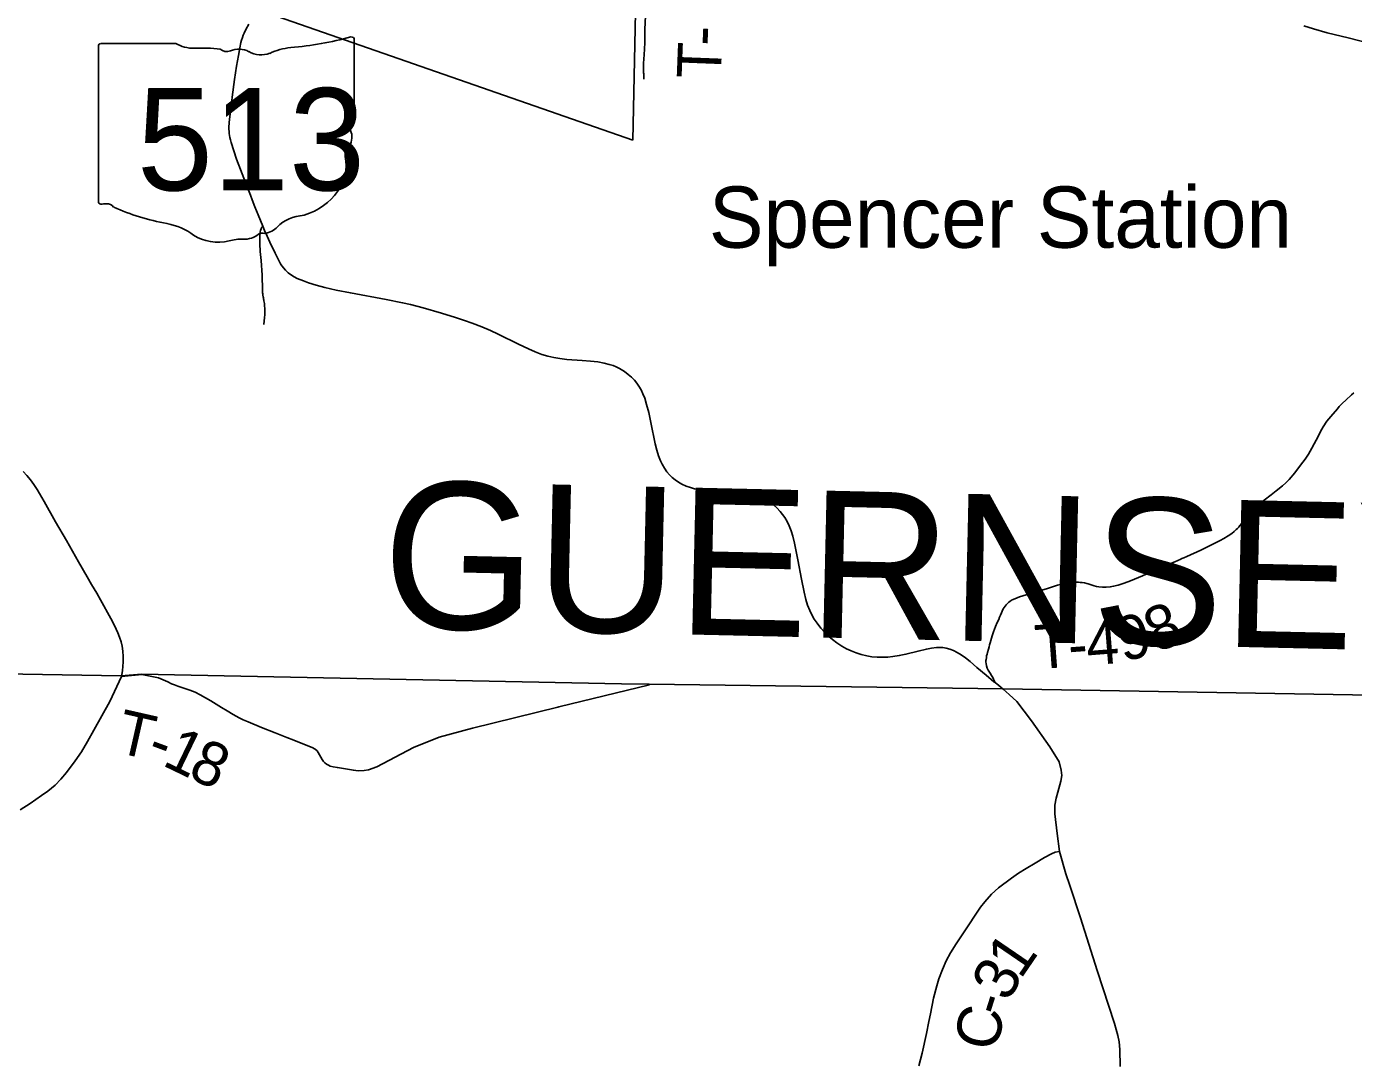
# Model space of a CAD drawing. Extents: x 0 to 34, y 0 to 22.
# Drawn here: x 3.375 to 5.085, y 18.658 to 19.997 of the extents above; entities that cross this region are included whole.
import ezdxf

# ---------------------------------------------------------------- set-up
doc = ezdxf.new("R2010")
doc.units = 0
for name, color, linetype in [('GM_X_Corporation', 7, 'Continuous'), ('GM_X_County_Road', 7, 'Continuous'), ('GM_X_County_Road_Text', 7, 'Continuous'), ('GM_X_County_Text', 7, 'Continuous'), ('GM_X_State_Location', 7, 'Continuous'), ('GM_X_State_Route', 7, 'Continuous'), ('GM_X_State_Shield', 7, 'Continuous'), ('GM_X_Township_Road', 7, 'Continuous'), ('GM_X_Township_Road_Text', 7, 'Continuous'), ('GM_X_Township_Text', 7, 'Continuous'), ('GM_X_Unincorporated_Text', 7, 'Continuous')]:
    doc.layers.add(name, color=color, linetype=linetype)

msp = doc.modelspace()

# ---------------------------------------------------------------- linework, layer by layer
at = {"layer": 'GM_X_Corporation'}
msp.add_lwpolyline([(4.156, 19.8502), (3.4056, 20.1119), (3.4116, 20.3825), (3.4113, 20.41), (3.4183, 20.6864), (3.5128, 20.6849), (3.6737, 20.6823), (4.1737, 20.6751), (4.1725, 20.6666), (4.1618, 20.1184)], close=True, dxfattribs=at)
at = {"layer": 'GM_X_County_Road'}
for points in [[(3.497, 19.1593), (3.498, 19.1637), (3.4985, 19.167), (3.499, 19.1718), (3.4994, 19.1781), (3.4993, 19.185), (3.4987, 19.1918), (3.4978, 19.1981), (3.4965, 19.2036), (3.4946, 19.2096), (3.4924, 19.2154), (3.4879, 19.225), (3.4834, 19.2339), (3.4701, 19.2579), (3.4652, 19.2665), (3.4585, 19.2777), (3.4528, 19.2874), (3.4416, 19.3067), (3.4261, 19.3343), (3.4121, 19.3585), (3.3974, 19.3845), (3.3883, 19.4), (3.3842, 19.4064), (3.3799, 19.4125), (3.3752, 19.4183), (3.3705, 19.4234)], [(3.3667, 18.9873), (3.3792, 18.9952), (3.3939, 19.0055), (3.4021, 19.0114), (3.4116, 19.0189), (3.419, 19.0266), (3.4263, 19.0354), (3.4374, 19.0504), (3.4455, 19.0621), (3.4533, 19.0752), (3.4616, 19.0899), (3.4821, 19.1267), (3.497, 19.1593)], [(4.7058, 18.9337), (4.7004, 18.9327), (4.6955, 18.9305), (4.6868, 18.9257), (4.6748, 18.9187), (4.663, 18.9118), (4.6533, 18.9056), (4.6443, 18.8991), (4.6275, 18.8868), (4.6184, 18.8784), (4.6098, 18.8687), (4.604, 18.8617), (4.5824, 18.8286), (4.5728, 18.8144), (4.5657, 18.803), (4.56, 18.7925), (4.5551, 18.7815), (4.5505, 18.7696), (4.5477, 18.7605), (4.5437, 18.7446), (4.5397, 18.7242), (4.5378, 18.7143), (4.5346, 18.6991), (4.5288, 18.6738), (4.5247, 18.6574)]]:
    msp.add_lwpolyline(points, dxfattribs=at)
at = {"layer": 'GM_X_State_Route'}
for points in [[(4.6229, 19.1512), (4.6215, 19.1523), (4.6114, 19.1606), (4.5996, 19.1708), (4.5907, 19.1785), (4.5849, 19.1831), (4.5794, 19.187), (4.5741, 19.1902), (4.5692, 19.1927), (4.5647, 19.1944), (4.56, 19.1957), (4.5558, 19.1963), (4.5521, 19.1965), (4.5473, 19.1964), (4.5412, 19.1957), (4.5345, 19.1945), (4.5237, 19.1918), (4.508, 19.1878), (4.4994, 19.186), (4.4914, 19.1848), (4.4846, 19.1841), (4.4783, 19.1839), (4.4708, 19.184), (4.464, 19.1846), (4.4578, 19.1856), (4.4504, 19.1873), (4.4439, 19.1894), (4.4375, 19.192), (4.4313, 19.1949), (4.4253, 19.1983), (4.419, 19.2024), (4.4136, 19.2066), (4.4088, 19.2106), (4.4035, 19.2159), (4.3985, 19.2215), (4.3936, 19.2279), (4.39, 19.2331), (4.3869, 19.2385), (4.3841, 19.2441), (4.3814, 19.2511), (4.3792, 19.2583), (4.3769, 19.268), (4.3736, 19.2845), (4.3688, 19.3095), (4.3645, 19.3308), (4.3623, 19.3398), (4.3601, 19.3468), (4.3576, 19.3531), (4.355, 19.3587), (4.3519, 19.364), (4.3492, 19.3681), (4.3461, 19.3719), (4.3419, 19.3763), (4.3373, 19.3803), (4.3323, 19.384), (4.3271, 19.3873), (4.3217, 19.3902), (4.3167, 19.3925), (4.3109, 19.3945), (4.305, 19.396), (4.2983, 19.3971), (4.2897, 19.3977), (4.273, 19.3983), (4.255, 19.3986), (4.2487, 19.3989), (4.2419, 19.3997), (4.2357, 19.401), (4.2303, 19.4025), (4.225, 19.4045), (4.2193, 19.4071), (4.2149, 19.4096), (4.2107, 19.4124), (4.2068, 19.4156), (4.2033, 19.4192), (4.2, 19.423), (4.1968, 19.4277), (4.1939, 19.4326), (4.1917, 19.4371), (4.1891, 19.4435), (4.1869, 19.4507), (4.1849, 19.4592), (4.1795, 19.4866), (4.1766, 19.4993), (4.1739, 19.5095), (4.1714, 19.5178), (4.1692, 19.5235), (4.1668, 19.5285), (4.164, 19.5332), (4.1612, 19.5373), (4.1581, 19.541), (4.1543, 19.545), (4.1501, 19.5485), (4.1452, 19.5521), (4.1389, 19.556), (4.1347, 19.5582), (4.1308, 19.5598), (4.1256, 19.5614), (4.119, 19.5631), (4.1112, 19.5645), (4.1014, 19.5656), (4.091, 19.5663), (4.0712, 19.5679), (4.0619, 19.5689), (4.0545, 19.5701), (4.0466, 19.5719), (4.0389, 19.5743), (4.0301, 19.5776), (4.0216, 19.5813), (4.0087, 19.5875), (3.9826, 19.6004), (3.9725, 19.6051), (3.9617, 19.6097), (3.949, 19.6146), (3.9391, 19.6181), (3.9274, 19.622), (3.9096, 19.6274), (3.8857, 19.6342), (3.8695, 19.6385), (3.8593, 19.6409), (3.838, 19.6451), (3.7922, 19.6535), (3.7739, 19.6572), (3.7593, 19.6606), (3.7479, 19.6637), (3.7383, 19.6666), (3.7318, 19.6689), (3.7237, 19.6723), (3.7198, 19.6742), (3.715, 19.6772), (3.712, 19.6796), (3.7083, 19.6829), (3.7039, 19.6883), (3.7022, 19.6909), (3.699, 19.697), (3.695, 19.7046), (3.6884, 19.7189), (3.6847, 19.7268), (3.6815, 19.734), (3.6791, 19.7394), (3.6731, 19.7541), (3.6689, 19.7645), (3.6654, 19.7737), (3.6632, 19.7795), (3.6599, 19.7882), (3.6504, 19.8125), (3.6455, 19.8259), (3.6419, 19.8365), (3.6385, 19.8472), (3.6376, 19.8508), (3.6369, 19.8537), (3.6364, 19.8565), (3.636, 19.8589), (3.6358, 19.8616), (3.6356, 19.8646), (3.6356, 19.8664), (3.6356, 19.8689), (3.6357, 19.871), (3.6359, 19.8733), (3.6377, 19.8881), (3.6384, 19.8934), (3.6388, 19.8979), (3.6393, 19.9016), (3.6398, 19.9059), (3.6428, 19.9286), (3.6454, 19.9456), (3.6477, 19.9596), (3.6495, 19.9694), (3.651, 19.9761), (3.6518, 19.9791), (3.6529, 19.9826), (3.654, 19.9856), (3.6552, 19.9885), (3.6573, 19.993), (3.661, 19.9998)], [(5.0207, 19.9976), (5.0332, 19.9938), (5.0511, 19.9889), (5.0782, 19.9821), (5.1096, 19.9743)], [(4.6336, 19.1427), (4.6279, 19.1475), (4.6229, 19.1512)], [(4.7842, 18.6565), (4.7836, 18.6785), (4.7828, 18.6884), (4.7813, 18.6964), (4.7769, 18.7119), (4.7546, 18.7801), (4.733, 18.8482), (4.7194, 18.8895), (4.7142, 18.9049), (4.7058, 18.9337), (4.7028, 18.9566), (4.7, 18.982), (4.6998, 18.9933), (4.7015, 19.0022), (4.7038, 19.0101), (4.7078, 19.0243), (4.7088, 19.0313), (4.7083, 19.0384), (4.7054, 19.0489), (4.6934, 19.0685), (4.67, 19.102), (4.6511, 19.1269), (4.641, 19.136), (4.6336, 19.1427)]]:
    msp.add_lwpolyline(points, dxfattribs=at)
at = {"layer": 'GM_X_State_Shield'}
for p, q in [((3.5672, 19.9751), (3.4707, 19.9751)), ((3.797, 19.8754), (3.797, 19.9801)), ((3.4674, 19.9717), (3.4674, 19.7716)), ((3.797, 19.8754), (3.797, 19.8754))]:
    msp.add_line(p, q, dxfattribs=at)
for centre, major_axis, start_param, end_param in [((3.4712, 19.9721), (0.00382, 0), 1.712693, 3.28349), ((3.5902, 19.9984), (0.037, 0), 4.042523, 4.731795), ((3.6796, 20.248), (0.3495, 0), 4.814394, 5.042369), ((3.7933, 19.9805), (0.00367, 0), 6.141152, 7.989035), ((3.6024, 19.8628), (0.133, 0), 1.404758, 1.657858), ((3.6326, 19.9732), (0.0107, 0), 3.836095, 5.185415), ((3.6483, 19.95), (0.0222, 0), 0.950623, 2.079405), ((3.677, 19.9818), (0.0267, 0), 4.081561, 5.145723), ((3.7242, 19.914), (0.0703, 0), 1.699011, 2.107814), ((3.7962, 19.8677), (0.00568, 0), 1.883978, 3.671073), ((3.7931, 19.875), (0.00393, 0), 5.05454, 6.418171), ((3.76, 19.8545), (0.0341, 0), 5.934695, 6.695948), ((3.8101, 19.8316), (0.0248, 0), 2.387724, 3.262537), ((3.6992, 19.8183), (0.0874, 0), 5.101752, 6.440018), ((3.4712, 19.7711), (0.00385, 0), 3.00124, 4.508301), ((3.4718, 19.7916), (0.0294, 0), 4.665946, 4.897461), ((3.4778, 19.76), (0.0106, 0), 0.519207, 1.627899), ((3.6117, 19.9398), (0.2524, 0), 4.195997, 4.488961), ((3.736, 19.7154), (0.0479, 0), 1.647645, 2.488434), ((3.5364, 19.6817), (0.079, 0), 0.823519, 1.323587), ((3.6754, 19.7522), (0.0282, 0), 4.937069, 5.64225), ((3.6218, 19.759), (0.0501, 0), 4.026481, 4.996735), ((3.6508, 19.6898), (0.0412, 0), 1.495662, 1.94098), ((3.6544, 19.744), (0.0267, 0), 4.691044, 5.507374), ((3.6786, 19.7247), (0.00752, 0), 1.147584, 2.315152)]:
    msp.add_ellipse(centre, major_axis=major_axis, ratio=0.8, start_param=start_param, end_param=end_param, dxfattribs=at)
at = {"layer": 'GM_X_Township_Road'}
msp.add_line((4.0606, 19.1199), (4.1775, 19.1485), dxfattribs=at)
for points in [[(4.1701, 19.9291), (4.1701, 19.9321), (4.1701, 19.9357), (4.17, 19.9374), (4.17, 19.9392), (4.1699, 19.941), (4.1698, 19.9428), (4.1698, 19.9447), (4.1699, 19.9473), (4.17, 19.9496), (4.1703, 19.9546), (4.1707, 19.9607), (4.1711, 19.9675), (4.1715, 19.9761), (4.1716, 19.9793), (4.1717, 19.9829), (4.1716, 19.986), (4.1716, 19.9896), (4.1717, 19.9921), (4.1717, 19.9934), (4.1725, 20.0101)], [(3.6807, 19.6127), (3.6814, 19.6217), (3.6817, 19.6252), (3.6819, 19.6278), (3.682, 19.6307), (3.6819, 19.6334), (3.6816, 19.6368), (3.6813, 19.6397), (3.681, 19.6416), (3.6807, 19.6432), (3.6805, 19.6445), (3.6803, 19.6456), (3.68, 19.647), (3.6797, 19.6483), (3.6794, 19.6504), (3.6792, 19.6522), (3.679, 19.6536), (3.6789, 19.6552), (3.6788, 19.6568), (3.6788, 19.6584), (3.6788, 19.6597), (3.6787, 19.6617), (3.6785, 19.6716), (3.6783, 19.6764), (3.6771, 19.6951), (3.676, 19.7068), (3.6754, 19.7168), (3.6754, 19.7249), (3.6755, 19.7277), (3.6758, 19.7304), (3.676, 19.7323), (3.6764, 19.7341), (3.6769, 19.7362), (3.6772, 19.737), (3.6775, 19.7376), (3.6779, 19.7383), (3.6784, 19.7389), (3.6791, 19.7394)], [(4.6229, 19.1512), (4.6209, 19.1557), (4.62, 19.1576), (4.6185, 19.1604), (4.6167, 19.1635), (4.6142, 19.1671), (4.6128, 19.1698), (4.6118, 19.1727), (4.6113, 19.1758), (4.6112, 19.1774), (4.6112, 19.1795), (4.6114, 19.1812), (4.6117, 19.1832), (4.6121, 19.1856), (4.6127, 19.188), (4.6133, 19.1902), (4.6143, 19.1942), (4.6152, 19.1973), (4.6158, 19.1998), (4.6166, 19.2026), (4.6174, 19.2053), (4.6184, 19.2087), (4.6193, 19.2114), (4.6202, 19.2143), (4.621, 19.2166), (4.6223, 19.22), (4.6237, 19.2235), (4.6258, 19.2286), (4.6276, 19.2326), (4.6287, 19.2355), (4.6298, 19.2382), (4.6311, 19.2412), (4.6323, 19.2435), (4.6336, 19.2461), (4.6348, 19.2479), (4.636, 19.2498), (4.6373, 19.2515), (4.6388, 19.253), (4.6406, 19.2547), (4.6426, 19.2562), (4.6452, 19.2578), (4.6486, 19.2594), (4.6543, 19.2616), (4.6674, 19.2657), (4.6805, 19.2696), (4.6846, 19.2709), (4.6894, 19.2722), (4.7035, 19.2767), (4.7102, 19.2787), (4.7134, 19.2794), (4.7155, 19.2798), (4.7175, 19.28), (4.7204, 19.2803), (4.7232, 19.2804), (4.7264, 19.2805), (4.7304, 19.2805), (4.7328, 19.2804), (4.7354, 19.2801), (4.7381, 19.2797), (4.741, 19.279), (4.7429, 19.2784), (4.7454, 19.2776), (4.7507, 19.276), (4.7535, 19.2752), (4.7567, 19.2746), (4.7613, 19.2742), (4.7661, 19.2742), (4.7714, 19.2746), (4.7756, 19.2754), (4.7816, 19.2769), (4.7893, 19.2793), (4.7975, 19.2823), (4.8129, 19.2888), (4.8232, 19.2934), (4.8368, 19.2992), (4.8481, 19.304), (4.8503, 19.305), (4.8526, 19.306), (4.8554, 19.3072), (4.8576, 19.3082), (4.8593, 19.309), (4.8616, 19.31), (4.8638, 19.311), (4.8661, 19.3119), (4.87, 19.3137), (4.875, 19.316), (4.8833, 19.3198), (4.8883, 19.322), (4.8925, 19.3241), (4.9009, 19.3283), (4.9054, 19.3305), (4.9087, 19.3321), (4.9132, 19.3344), (4.9178, 19.3371), (4.9232, 19.3404), (4.928, 19.3436), (4.9312, 19.346), (4.9338, 19.3484), (4.9353, 19.3498), (4.9362, 19.3508), (4.9369, 19.3517), (4.9377, 19.3526), (4.9386, 19.3537), (4.9394, 19.3547), (4.9402, 19.3558), (4.9413, 19.3571), (4.9439, 19.3602), (4.9462, 19.3629), (4.9478, 19.3645), (4.9494, 19.3663), (4.9519, 19.3689), (4.955, 19.3719), (4.9583, 19.3755), (4.9636, 19.3807), (4.9668, 19.3838), (4.9696, 19.3862), (4.9788, 19.3934), (4.9852, 19.3984), (4.9934, 19.4049), (4.9976, 19.4086), (5.0019, 19.4131), (5.0091, 19.4217), (5.0167, 19.4314), (5.0226, 19.4394), (5.0267, 19.4456), (5.0314, 19.4536), (5.0397, 19.4695), (5.0424, 19.4751), (5.0439, 19.4778), (5.0458, 19.481), (5.0506, 19.4881), (5.0556, 19.4944), (5.0641, 19.5041), (5.0666, 19.5069), (5.0708, 19.5114), (5.0748, 19.5152), (5.0824, 19.5223), (5.0852, 19.5247)], [(3.497, 19.1593), (3.5232, 19.1618), (3.5447, 19.1573), (3.5567, 19.1523), (3.5616, 19.1498), (3.5654, 19.1482), (3.5695, 19.1466), (3.5787, 19.1437), (3.5853, 19.1416), (3.5919, 19.1388), (3.5983, 19.1354), (3.6122, 19.1276), (3.6259, 19.119), (3.6332, 19.1147), (3.6411, 19.1102), (3.6489, 19.1056), (3.6541, 19.1031), (3.6602, 19.1005), (3.6775, 19.0933), (3.695, 19.0865), (3.7101, 19.0806), (3.7191, 19.0769), (3.7307, 19.0724), (3.7429, 19.0675), (3.7469, 19.0653), (3.7491, 19.0633), (3.7506, 19.061), (3.7541, 19.055), (3.7556, 19.0519), (3.7575, 19.0497), (3.7593, 19.0479), (3.7614, 19.0463), (3.7638, 19.0448), (3.7661, 19.0437), (3.7697, 19.0427), (3.7754, 19.0417), (3.7832, 19.0406), (3.7959, 19.0383), (3.8022, 19.0377), (3.8097, 19.0379), (3.8153, 19.0386), (3.8263, 19.0425), (3.8733, 19.0674), (3.9065, 19.0808), (3.9494, 19.0926), (4.0596, 19.1196), (4.0606, 19.1199)]]:
    msp.add_lwpolyline(points, dxfattribs=at)
at = {"layer": 'GM_X_Township_Text'}
msp.add_lwpolyline([(2.1, 19.1775), (2.6044, 19.174), (2.6249, 19.1744), (2.7359, 19.1727), (3.4968, 19.1598), (3.523, 19.1623), (4.1413, 19.1495), (4.1773, 19.1491), (4.6334, 19.1433), (5.5591, 19.1275), (6.3618, 19.1099), (6.6786, 19.1086), (6.7436, 19.1061), (6.828, 19.1033), (6.8907, 19.103), (7.1115, 19.0999), (7.1957, 19.0991), (7.1974, 19.2018), (7.1981, 19.2461), (7.1982, 19.2496), (7.2244, 20.2649), (7.231, 20.9)], dxfattribs=at)

# ---------------------------------------------------------------- texts
at = {"layer": 'GM_X_County_Road_Text'}
for s, rotation, p in [('1', 55.6662, (4.6557, 18.7677)), ('3', 61.9826, (4.6401, 18.7382)), ('-', 72.5426, (4.6342, 18.7185)), ('C', 77.8924, (4.6247, 18.6742))]:
    msp.add_text(s, height=0.0568, rotation=rotation, dxfattribs=at).set_placement(p)
at = {"layer": 'GM_X_County_Text'}
msp.add_text('GUERNSEY COUNTY', height=0.189394, rotation=358.7038, dxfattribs=at).set_placement((3.8321, 19.2222))
at = {"layer": 'GM_X_State_Location'}
for s in ['s', 'r']:
    msp.add_text(s, height=0.000189, dxfattribs=at).set_placement((3.6285, 19.8583))
msp.add_text('513', height=0.000189, rotation=0, dxfattribs=at).set_placement((3.5616, 19.8445))
at = {"layer": 'GM_X_State_Shield'}
msp.add_text('513', height=0.13184, dxfattribs=at).set_placement((3.5169, 19.7857))
at = {"layer": 'GM_X_Township_Road_Text'}
for s, rotation, p in [('-', 87.603, (4.271, 19.9712)), ('T', 87.7794, (4.2694, 19.9288)), ('9', 14.0921, (4.7875, 19.1777)), ('8', 22.4005, (4.8299, 19.189)), ('T', 4.1885, (4.6763, 19.1684)), ('4', 4.4909, (4.7423, 19.1733)), ('-', 4.2457, (4.7188, 19.1715)), ('T', 347.2039, (3.4878, 19.0618)), ('1', 334.2402, (3.548, 19.0454)), ('-', 339.5801, (3.5274, 19.053)), ('8', 335.6277, (3.5808, 19.0296))]:
    msp.add_text(s, height=0.0568, rotation=rotation, dxfattribs=at).set_placement(p)
at = {"layer": 'GM_X_Unincorporated_Text'}
msp.add_text('Spencer Station', height=0.078977, rotation=0, dxfattribs=at).set_placement((4.2541, 19.7117))

doc.saveas('drawing.dxf')
